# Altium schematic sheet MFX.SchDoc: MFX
size A4; DocumentNumber: MB1165; Revision: C.1; SheetNumber: 16; SheetTotal: 17; Project: STM32469I-EVAL
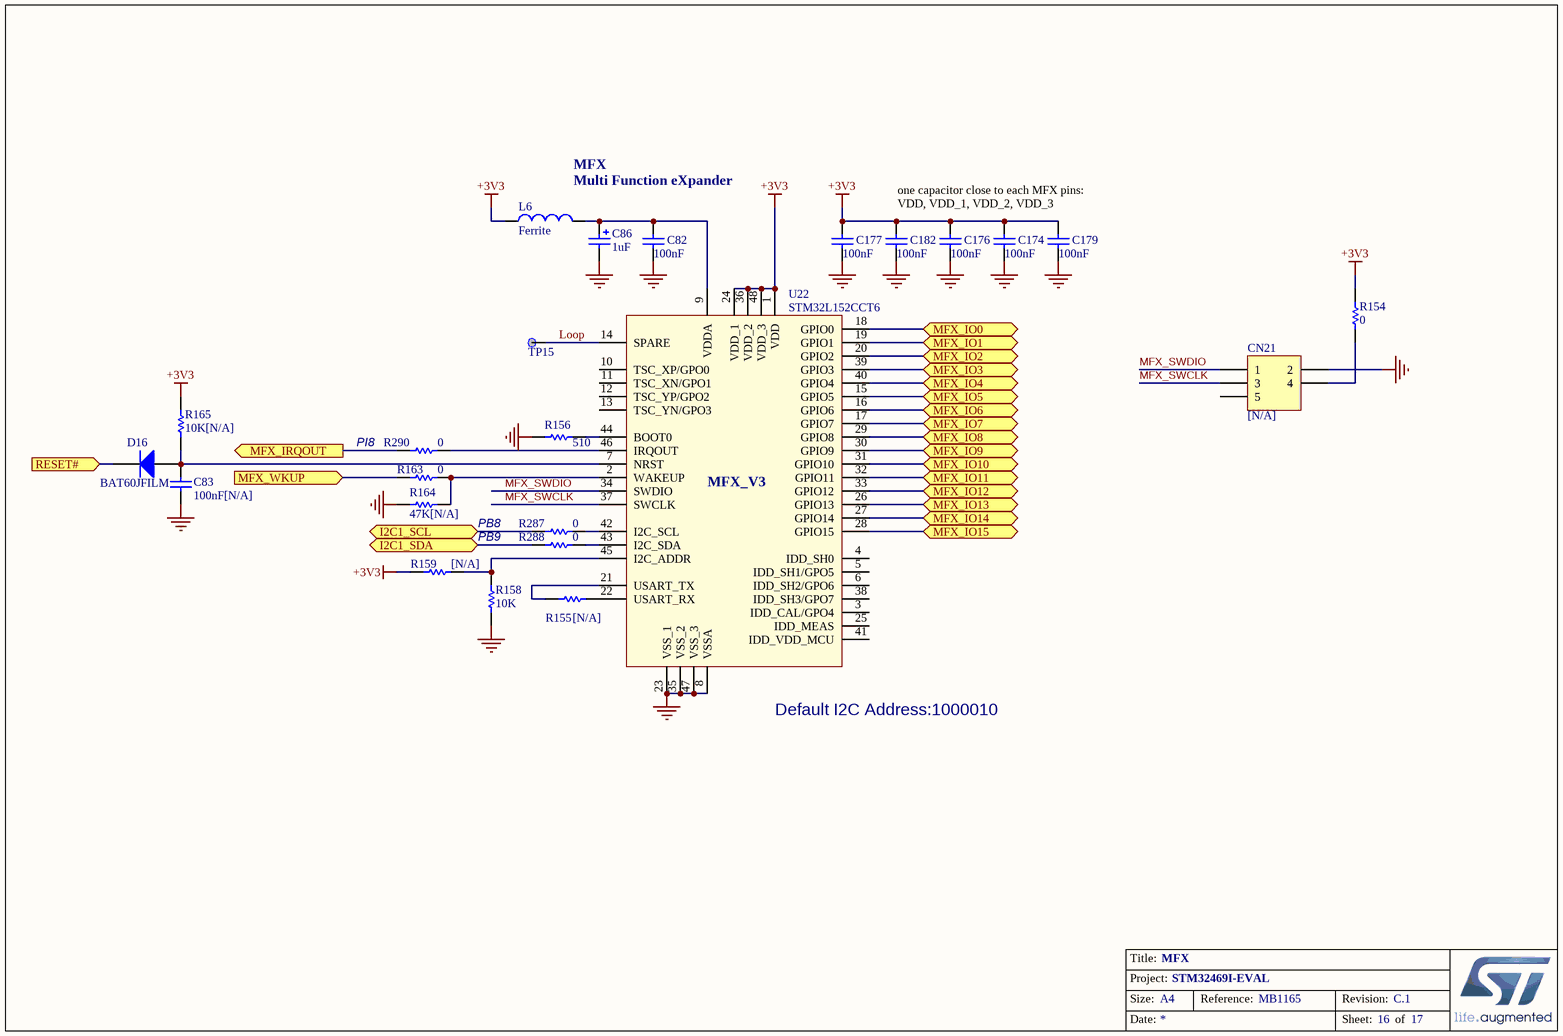
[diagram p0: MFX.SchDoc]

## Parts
C82  100nF  [0402C]
C83  100nF[N/A]  [0402C]
C86  1uF  [TAN-A]
C174  100nF  [0402C]
C176  100nF  [0402C]
C177  100nF  [0402C]
C179  100nF  [0402C]
C182  100nF  [0402C]
CN21  [N/A]  [HDR_2X3-1_2R54-6]
D16  BAT60JFILM  [SOD-323]
L6  Ferrite  [0603L]
R154  0  [0603R]
R155  [N/A]  [0603R]
R156  510  [0402R]
R158  10K  [0402R]
R159  [N/A]  [0603R]
R163  0  [0603R]
R164  47K[N/A]  [0402R]
R165  10K[N/A]  [0402R]
R287  0  [0603R]
R288  0  [0603R]
R290  0  [0603R]
TP15  (no value)  [TP]
U22  STM32L152CCT6  [LQFP48_0R5_9X9]

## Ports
I2C1_SCL (bidir), I2C1_SDA (bidir), MFX_IO0 (bidir), MFX_IO1 (bidir), MFX_IO2 (bidir), MFX_IO3 (bidir), MFX_IO4 (bidir), MFX_IO5 (bidir), MFX_IO6 (bidir), MFX_IO7 (bidir), MFX_IO8 (bidir), MFX_IO9 (bidir), MFX_IO10 (bidir), MFX_IO11 (bidir), MFX_IO12 (bidir), MFX_IO13 (bidir), MFX_IO14 (bidir), MFX_IO15 (bidir), MFX_IRQOUT (out), MFX_WKUP (in), RESET# (in)

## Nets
+3V3: C174.2 C176.1 C177.2 C179.2 C182.2 L6.1 R154.1 R159.2 R165.2 U22.1(VDD) U22.24(VDD_1) U22.36(VDD_2) U22.48(VDD_3)
GND: C82.1 C83.1 C86.2 C174.1 C176.2 C177.1 C179.1 C182.1 CN21.2 R156.2 R158.2 R164.1 U22.8(VSSA) U22.23(VSS_1) U22.35(VSS_2) U22.47(VSS_3)
I2C1_SCL: R287.1 ; port I2C1_SCL
I2C1_SDA: R288.1 ; port I2C1_SDA
Loop: TP15.1 U22.14(SPARE)
MFX_IO0: U22.18(GPIO0) ; port MFX_IO0
MFX_IO1: U22.19(GPIO1) ; port MFX_IO1
MFX_IO2: U22.20(GPIO2) ; port MFX_IO2
MFX_IO3: U22.39(GPIO3) ; port MFX_IO3
MFX_IO4: U22.40(GPIO4) ; port MFX_IO4
MFX_IO5: U22.15(GPIO5) ; port MFX_IO5
MFX_IO6: U22.16(GPIO6) ; port MFX_IO6
MFX_IO7: U22.17(GPIO7) ; port MFX_IO7
MFX_IO8: U22.29(GPIO8) ; port MFX_IO8
MFX_IO9: U22.30(GPIO9) ; port MFX_IO9
MFX_IO10: U22.31(GPIO10) ; port MFX_IO10
MFX_IO11: U22.32(GPIO11) ; port MFX_IO11
MFX_IO12: U22.33(GPIO12) ; port MFX_IO12
MFX_IO13: U22.26(GPIO13) ; port MFX_IO13
MFX_IO14: U22.27(GPIO14) ; port MFX_IO14
MFX_IO15: U22.28(GPIO15) ; port MFX_IO15
MFX_IRQOUT: R290.1 ; port MFX_IRQOUT
MFX_SWCLK: CN21.3 U22.37(SWCLK)
MFX_SWDIO: CN21.1 U22.34(SWDIO)
MFX_WKUP: R163.2 ; port MFX_WKUP
RESET#: D16.2(K) ; port RESET#
NetC82_2: C82.2 C86.1 L6.2 U22.9(VDDA)
NetC83_2: C83.2 D16.1(A) R165.1 U22.7(NRST)
NetCN21_4: CN21.4 R154.2
NetR155_1: R155.1 U22.21(USART_TX)
NetR155_2: R155.2 U22.22(USART_RX)
NetR156_1: R156.1 U22.44(BOOT0)
NetR158_1: R158.1 R159.1 U22.45(I2C_ADDR)
NetR163_1: R163.1 R164.2 U22.2(WAKEUP)
NetR287_2: R287.2 U22.42(I2C_SCL)
NetR288_2: R288.2 U22.43(I2C_SDA)
NetR290_2: R290.2 U22.46(IRQOUT)

Not connected (* = marked no-connect by the designer): CN21 5; U22 3(IDD_CAL/GPO4) 4(IDD_SH0) 5(IDD_SH1/GPO5) 6(IDD_SH2/GPO6) 10(TSC_XP/GPO0) 11(TSC_XN/GPO1) 12(TSC_YP/GPO2) 13(TSC_YN/GPO3) 25(IDD_MEAS) 38(IDD_SH3/GPO7) 41(IDD_VDD_MCU)

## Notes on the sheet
- MFX
  Multi Function eXpander
- one capacitor close to each MFX pins: VDD, VDD_1, VDD_2, VDD_3
- PI8
- PB8
- PB9
- (near U22) Default I2C Address:1000010

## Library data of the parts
C82 C83 C174 C176 C177 C179 C182 = Cap_100nF_X7R_10%_0402: Capacitor,100nF,16V,X7R,10%,0402,YAGEO; Manuf_Part_1: CC0402KRX7R7BB104
C86 = Cap_1uF_POL_10%_TANA: Polarized Capacitor,1uF,16V,10%,typeA,AVX; Manuf_Part_1: TAJA105K016R
CN21 = Header 3X2: Header, 3-Pin, Dual row
D16 = Diode: Default Diode; Code - JEDEC: DO-214-AB
L6 = BEAD_600R_350MA_0603: Bead,600R,350mA,0603,FCM1608KF-601T03,Tai-tech; Manuf_2: TDK; Manuf_Part_2: MPZ1608S300A; Value: 100uH; Comment_1: bead,30R,5A,0603,MPZ1608S300A,TDK
R154 R287 R288 R290 = Res1: Resistor; Value: 1K; Ordered by: Subcon
R155 = res1: Resistor; Value: 1K; Ordered by: Subcon
R156 R164 R165 = Resistor_ST: Resistor 0402 / 0603 / 0805; Description: Resistor 0402 or 0603 or 0805; Value: 10K
R158 = Resistor_ST: Resistor 0402 / 0603 / 0805; Description: Resistor 0402 or 0603 or 0805
R159 R163 = Res1: Resistor; Value: 1K
TP15 = TP
U22 = MFX: Multifunction expander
